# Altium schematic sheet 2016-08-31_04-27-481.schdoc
size 340 x 134 mm; SheetNumber: 1; SheetTotal: 1
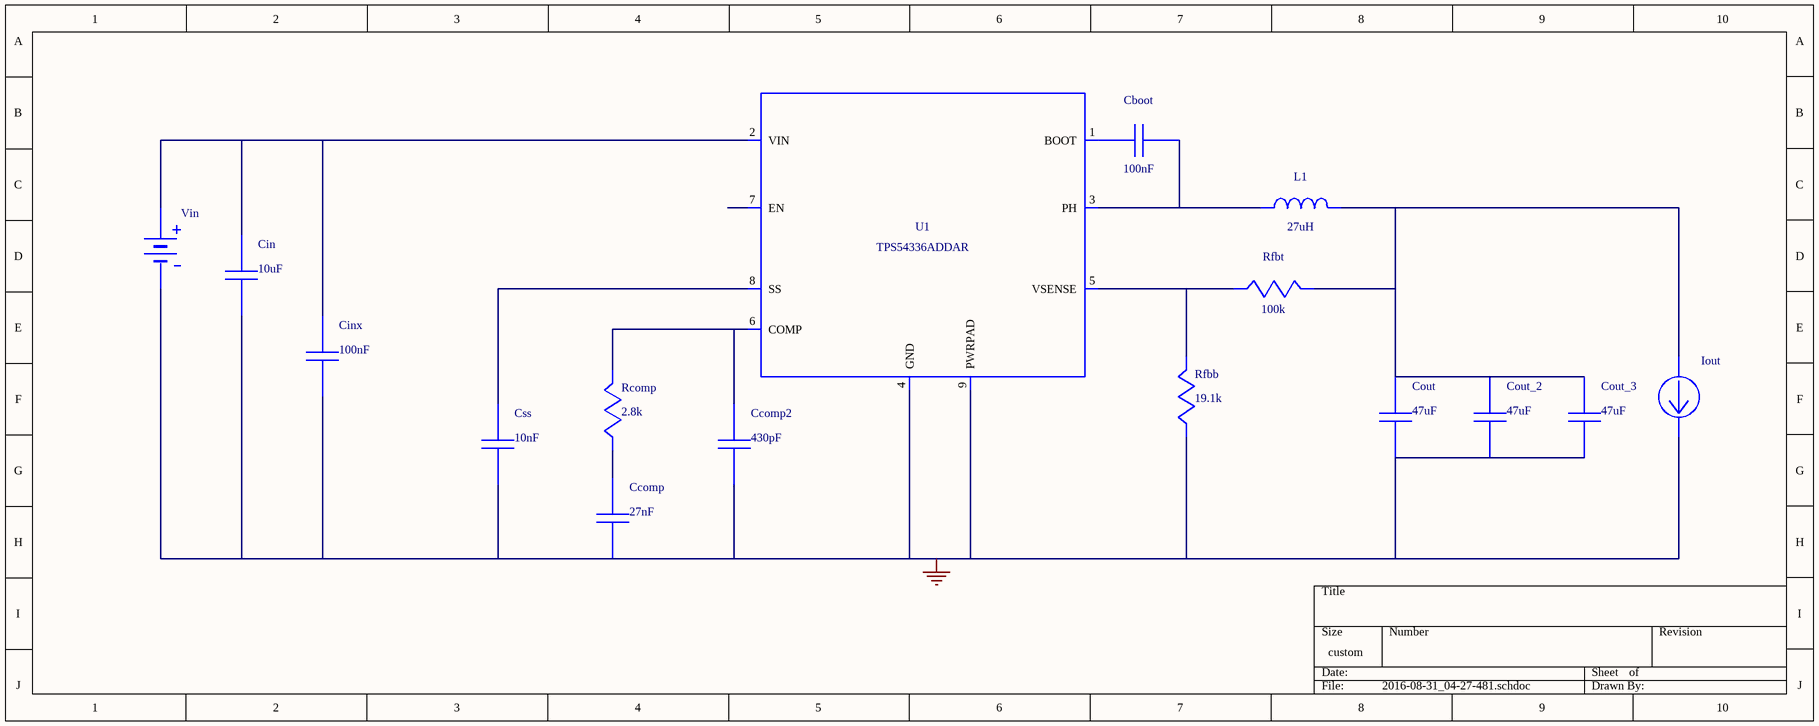
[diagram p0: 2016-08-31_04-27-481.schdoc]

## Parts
Cboot  value 100nF  (hidden comment: C0805C104K5RACTU)
Ccomp  value 27nF  (hidden comment: GRM155R61A273KA01D)
Ccomp2  value 430pF  (hidden comment: GRM1555C1E431JA01D)
Cin  value 10uF  (hidden comment: GRM31CR71E106KA12L)
Cinx  value 100nF  (hidden comment: C0805C104K5RACTU)
Cout  value 47uF  (hidden comment: GRM31CR61A476KE15L)
Cout_2  value 47uF  (hidden comment: GRM31CR61A476KE15L)
Cout_3  value 47uF  (hidden comment: GRM31CR61A476KE15L)
Css  value 10nF  (hidden comment: GRM033R61A103KA01D)
Iout  WB_CURRENT_LOAD  (value not drawn)
L1  value 27uH  (hidden comment: SDR1307-270ML)
Rcomp  value 2.8k  (hidden comment: CRCW04022K80FKED)
Rfbb  value 19.1k  (hidden comment: CRCW040219K1FKED)
Rfbt  value 100k  (hidden comment: CRCW0402100KFKED)
U1  TPS54336DDAR  (value not drawn)
Vin  WB_BATTERY  (value not drawn)

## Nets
0: Ccomp.2 Ccomp2.2 Cin.2 Cinx.2 Cout.2 Cout_2.2 Cout_3.2 Css.2 Iout.2(-) Rfbb.2 U1.4(GND) U1.9(PWRPAD) Vin.2(-)
NetCboot_1: Cboot.1 U1.1(BOOT)
NetCboot_2: Cboot.2 L1.1 U1.3(PH)
NetCcomp2_1: Ccomp2.1 Rcomp.1 U1.6(COMP)
NetCcomp_1: Ccomp.1 Rcomp.2
NetCin_1: Cin.1 Cinx.1 U1.2(VIN) Vin.1(+)
NetCout_1: Cout.1 Cout_2.1 Cout_3.1 Iout.1(+) L1.2 Rfbt.1
NetCss_1: Css.1 U1.8(SS)
NetRfbb_1: Rfbb.1 Rfbt.2 U1.5(VSENSE)

Not connected (* = marked no-connect by the designer): U1 7(EN)

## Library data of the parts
Cboot Cinx = C0805C104K5RACTU: Manufacturer Name: Kemet
Ccomp = GRM155R61A273KA01D: GRM155R61A273KA0; Manufacturer Name: MuRata
Ccomp2 = GRM1555C1E431JA01D: GRM1555C1E431JA0; Manufacturer Name: MuRata
Cin = GRM31CR71E106KA12L: GRM31CR71E106KA1; Manufacturer Name: MuRata
Cout Cout_2 Cout_3 = GRM31CR61A476KE15L: GRM31CR61A476KE1; Manufacturer Name: MuRata
Css = GRM033R61A103KA01D: GRM033R61A103KA0; Manufacturer Name: MuRata
L1 = SDR1307-270ML: Manufacturer Name: Bourns
Rcomp = CRCW04022K80FKED: Manufacturer Name: Vishay-Dale
Rfbb = CRCW040219K1FKED: Manufacturer Name: Vishay-Dale
Rfbt = CRCW0402100KFKED: Manufacturer Name: Vishay-Dale
U1 = TPS54336DDAR: TPS54336ADDAR; Manufacturer Name: Texas Instruments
